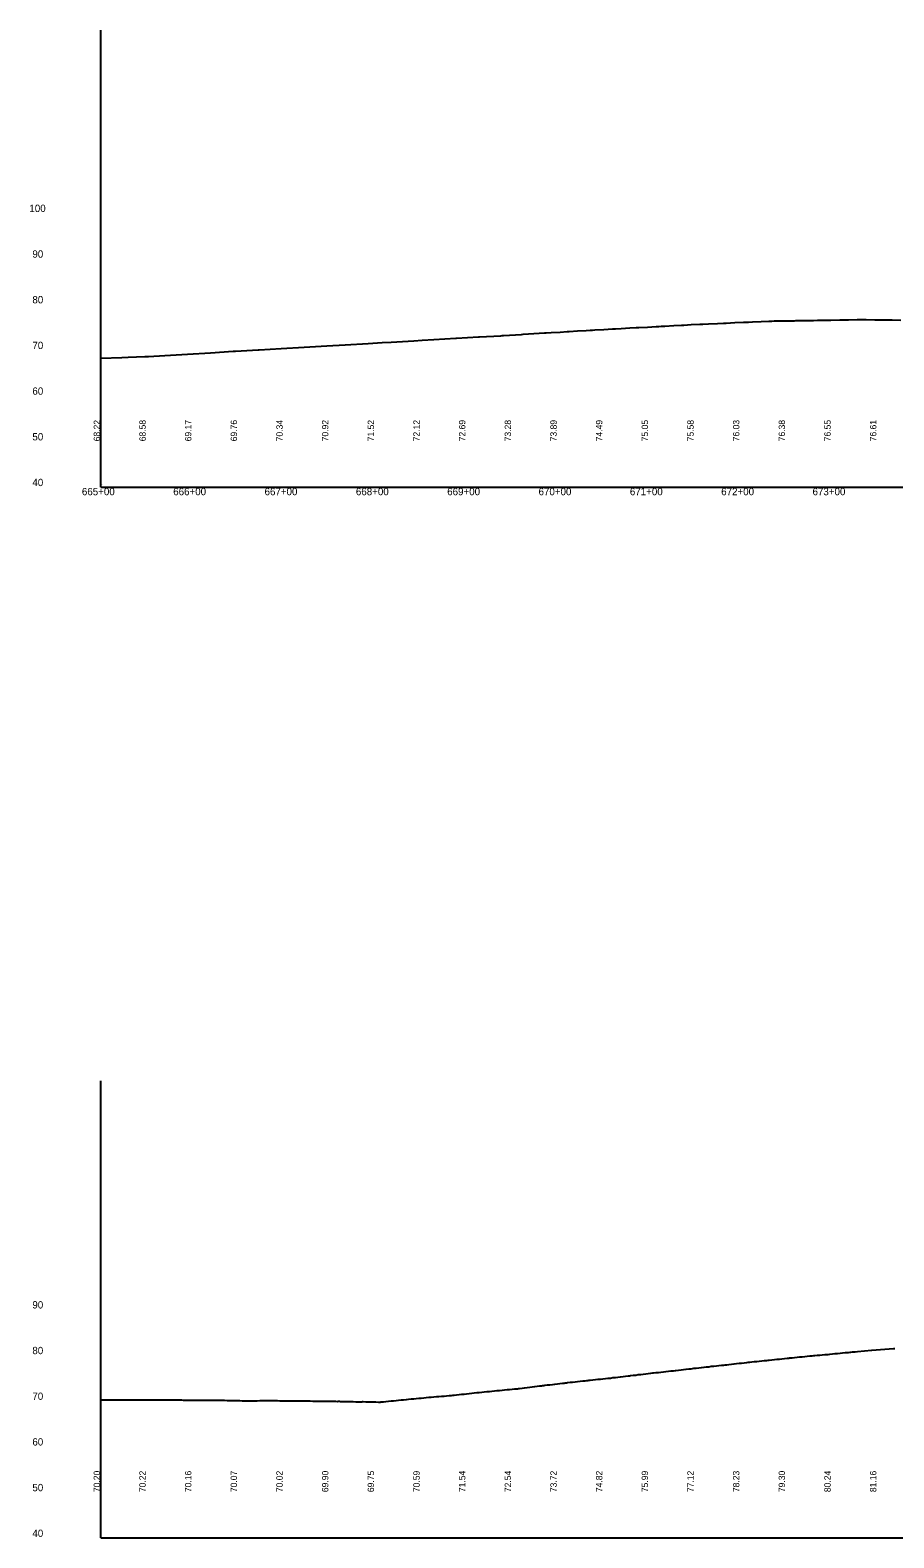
# Model space of a CAD drawing. Extents: x 2526761 to 2530854, y 882903 to 888012.
# Drawn here: x 2526761 to 2527707, y 886362 to 888012 of the extents above; entities that cross this region are included whole.
import ezdxf

# ---------------------------------------------------------------- set-up
doc = ezdxf.new("R2010")
doc.units = 0
for name, color, linetype in [('RD_DDB_ElevTX', 7, 'Continuous'), ('RD_DDB_Profile_EX', 7, 'Continuous'), ('RD_DDB_StaTX', 7, 'Continuous'), ('RD_DDB_StripGrade', 7, 'Continuous'), ('RD_GPK_Profile_Cell', 7, 'Continuous')]:
    doc.layers.add(name, color=color, linetype=linetype)

msp = doc.modelspace()

# ---------------------------------------------------------------- linework, layer by layer
at = {"layer": 'RD_DDB_Profile_EX'}
for points in [[(2526839, 887653.2), (2526862, 887654), (2526868.8, 887654.2), (2526887, 887654.9), (2526891, 887655.1), (2526908.8, 887656.1), (2526933.8, 887657.6), (2526958.8, 887659.1), (2526983.8, 887660.6), (2526986.4, 887660.8), (2527011.3, 887662.2), (2527012.2, 887662.3), (2527036.4, 887663.6), (2527061.4, 887665.1), (2527086.3, 887666.5), (2527106.5, 887667.7), (2527131.5, 887669.2), (2527147, 887670.2), (2527156.6, 887670.8), (2527181.5, 887672.2), (2527190.6, 887672.8), (2527203.3, 887673.5), (2527227.7, 887674.9), (2527228.3, 887674.9), (2527252.2, 887676.3), (2527253.3, 887676.4), (2527276.8, 887677.7), (2527278.3, 887677.8), (2527279.6, 887677.9), (2527299.5, 887679.1), (2527301.1, 887679.2), (2527324.5, 887680.7), (2527326.3, 887680.8), (2527332.1, 887681.1), (2527341.7, 887681.7), (2527349.5, 887682.2), (2527351.5, 887682.3), (2527360.8, 887682.9), (2527370.4, 887683.5), (2527374.5, 887683.7), (2527374.8, 887683.7), (2527377.2, 887683.9), (2527379.9, 887684), (2527389.5, 887684.6), (2527399.1, 887685.1), (2527400.1, 887685.2), (2527402.2, 887685.3), (2527408.6, 887685.6), (2527418.2, 887686.2), (2527425, 887686.6), (2527427.2, 887686.7), (2527427.8, 887686.7), (2527437.3, 887687.2), (2527446.9, 887687.8), (2527449.9, 887687.9), (2527452.2, 887688.1), (2527456.5, 887688.3), (2527466.1, 887688.8), (2527474.7, 887689.3), (2527475.6, 887689.4), (2527477.2, 887689.4), (2527485.2, 887689.8), (2527494.8, 887690.2), (2527496, 887690.3), (2527498, 887690.4), (2527504.3, 887690.7), (2527513.9, 887691.1), (2527520.6, 887691.4), (2527523, 887691.5), (2527523.5, 887691.5), (2527533, 887692), (2527542.6, 887692.4), (2527545.6, 887692.5), (2527548, 887692.6), (2527552.2, 887692.8), (2527561.8, 887693.2), (2527570.4, 887693.6), (2527571.3, 887693.6), (2527573, 887693.7), (2527573.5, 887693.7), (2527576.1, 887693.8), (2527580.9, 887693.9), (2527590.5, 887694), (2527598.5, 887694.1), (2527600, 887694.2), (2527601.1, 887694.2), (2527609.6, 887694.3), (2527619.2, 887694.5), (2527623.5, 887694.6), (2527626.3, 887694.6), (2527628.7, 887694.6), (2527638.3, 887694.8), (2527647.9, 887695), (2527648.4, 887695), (2527651.6, 887695), (2527657.4, 887695.1), (2527667, 887695.3), (2527673.4, 887695.4), (2527676.8, 887695.3), (2527686.2, 887695.2), (2527695.7, 887695)], [(2527695.7, 887695), (2527697.7, 887695), (2527700.7, 887694.9), (2527705.3, 887694.9), (2527714.9, 887694.7)], [(2527543.2, 886553.7), (2527546, 886554), (2527547.5, 886554.2), (2527548.7, 886554.3), (2527549.4, 886554.4), (2527551.5, 886554.6), (2527554.3, 886554.9), (2527557, 886555.2), (2527559.8, 886555.5), (2527562.5, 886555.7), (2527565.3, 886556), (2527567.5, 886556.2), (2527568.1, 886556.3), (2527569.4, 886556.4), (2527570.8, 886556.6), (2527573.6, 886556.9), (2527576.4, 886557.2), (2527579.1, 886557.5), (2527581.9, 886557.8), (2527584.6, 886558.1), (2527587.4, 886558.4), (2527590.2, 886558.7), (2527592.4, 886558.9), (2527592.9, 886559), (2527595.8, 886559.2), (2527598.4, 886559.5), (2527601.2, 886559.8), (2527604, 886560.1), (2527606.7, 886560.3), (2527609.5, 886560.6), (2527612.3, 886560.9), (2527615, 886561.1), (2527617.4, 886561.4), (2527617.8, 886561.4), (2527619.5, 886561.5), (2527620.5, 886561.6), (2527623.3, 886561.9), (2527626.1, 886562.1), (2527628.8, 886562.4), (2527631.6, 886562.6), (2527632.5, 886562.7), (2527634.3, 886562.9), (2527635.2, 886562.9), (2527637.1, 886563.1), (2527639.9, 886563.4), (2527642.6, 886563.7), (2527645.4, 886563.9), (2527648.2, 886564.2), (2527650.9, 886564.5), (2527653.7, 886564.8), (2527656.4, 886565), (2527657.5, 886565.1), (2527659.2, 886565.2), (2527660.1, 886565.3), (2527662, 886565.5), (2527664.7, 886565.7), (2527667.5, 886566), (2527682.5, 886567.4), (2527683.2, 886567.4), (2527706.8, 886569.2), (2527708.2, 886569.3)], [(2527308.5, 886527), (2527311.2, 886527.3), (2527314, 886527.7), (2527316.7, 886528), (2527319.5, 886528.4), (2527321.3, 886528.6), (2527322.3, 886528.7), (2527323.8, 886528.9), (2527325, 886529), (2527327.8, 886529.4), (2527330.6, 886529.7), (2527333.3, 886530), (2527336.1, 886530.4), (2527338.8, 886530.7), (2527341.6, 886531), (2527344.4, 886531.3), (2527346, 886531.5), (2527347.1, 886531.6), (2527349.3, 886531.9), (2527349.9, 886532), (2527352.6, 886532.3), (2527355.4, 886532.6), (2527358.2, 886532.9), (2527360.9, 886533.2), (2527363.7, 886533.5), (2527366.5, 886533.8), (2527369.2, 886534.1), (2527371, 886534.3), (2527372, 886534.4), (2527373.3, 886534.6), (2527374.7, 886534.7), (2527377.5, 886535), (2527380.3, 886535.3), (2527383, 886535.6), (2527385.8, 886535.9), (2527388.5, 886536.1), (2527391.3, 886536.4), (2527394.1, 886536.7), (2527394.6, 886536.8), (2527396.8, 886537), (2527399.6, 886537.4), (2527402.4, 886537.7), (2527405.1, 886538), (2527407.9, 886538.4), (2527410.6, 886538.7), (2527413.4, 886539), (2527416.2, 886539.3), (2527417.2, 886539.4), (2527417.7, 886539.5), (2527418.9, 886539.7), (2527421.7, 886540), (2527424.5, 886540.3), (2527427.2, 886540.7), (2527430, 886541), (2527432.7, 886541.3), (2527435.5, 886541.6), (2527438.3, 886541.9), (2527441, 886542.3), (2527443.2, 886542.6), (2527443.8, 886542.6), (2527446.5, 886542.9), (2527449.3, 886543.2), (2527452.1, 886543.5), (2527454.8, 886543.8), (2527457.6, 886544.1), (2527460.4, 886544.4), (2527463.1, 886544.7), (2527466, 886545), (2527468.2, 886545.3), (2527468.6, 886545.3), (2527471.4, 886545.6), (2527474.3, 886545.9), (2527476.9, 886546.2), (2527479.7, 886546.6), (2527482.5, 886546.9), (2527485.2, 886547.2), (2527488, 886547.6), (2527490.7, 886547.9), (2527493.5, 886548.2), (2527496.3, 886548.5), (2527496.7, 886548.6), (2527499, 886548.8), (2527499.3, 886548.9), (2527501.8, 886549.1), (2527504.5, 886549.4), (2527507.3, 886549.8), (2527510.1, 886550.1), (2527512.8, 886550.3), (2527515.6, 886550.6), (2527518.4, 886550.9), (2527521.1, 886551.2), (2527522.5, 886551.4), (2527523.9, 886551.5), (2527524.4, 886551.6), (2527526.6, 886551.8), (2527529.4, 886552.1), (2527532.2, 886552.5), (2527534.9, 886552.8), (2527537.7, 886553.1), (2527540.4, 886553.4), (2527543.2, 886553.7)], [(2526839, 886513.1), (2526841.7, 886513.1), (2526844.5, 886513.1), (2526847.2, 886513.1), (2526850, 886513.1), (2526852.8, 886513.1), (2526855.7, 886513.1), (2526856.9, 886513.1), (2526858.3, 886513.1), (2526861, 886513.1), (2526863.8, 886513.2), (2526866.6, 886513.2), (2526869.3, 886513.2), (2526872.1, 886513.2), (2526874.9, 886513.2), (2526877.6, 886513.2), (2526880.4, 886513.2), (2526880.8, 886513.2), (2526883.1, 886513.2), (2526884.5, 886513.2), (2526884.9, 886513.2), (2526885.9, 886513.2), (2526888.7, 886513.2), (2526891.4, 886513.2), (2526894.2, 886513.2), (2526897, 886513.1), (2526899.7, 886513.1), (2526902.5, 886513.1), (2526905.2, 886513.1), (2526907, 886513.1), (2526908, 886513.1), (2526910.9, 886513.1), (2526913.5, 886513.1), (2526916.3, 886513), (2526919, 886513), (2526921.8, 886513), (2526924.6, 886513), (2526927.3, 886513), (2526929.1, 886512.9), (2526930.1, 886512.9), (2526932.9, 886512.9), (2526935.6, 886512.9), (2526937.4, 886512.9), (2526938.4, 886512.9), (2526941.1, 886512.9), (2526943.9, 886512.8), (2526946.7, 886512.8), (2526949.4, 886512.8), (2526950.5, 886512.8), (2526952.2, 886512.8), (2526954.9, 886512.7), (2526957.7, 886512.7), (2526960.5, 886512.7), (2526963.2, 886512.7), (2526964.6, 886512.7), (2526966, 886512.7), (2526968.8, 886512.6), (2526971.5, 886512.6), (2526974.3, 886512.6), (2526977, 886512.5), (2526979.8, 886512.5), (2526982.6, 886512.5), (2526985.3, 886512.5), (2526988.5, 886512.5), (2526990.9, 886512.4), (2526993.6, 886512.2), (2526996.4, 886512.1), (2526999.1, 886512), (2526999.9, 886512), (2527001.9, 886512), (2527004.7, 886512.1), (2527007.4, 886512.2), (2527010.2, 886512.2), (2527012.9, 886512.3), (2527015.7, 886512.4), (2527018, 886512.4), (2527018.5, 886512.4), (2527021.2, 886512.4), (2527023, 886512.3), (2527024, 886512.3), (2527024.7, 886512.3), (2527026.8, 886512.3), (2527029.5, 886512.3), (2527032.3, 886512.3), (2527035, 886512.2), (2527037.8, 886512.2), (2527040.6, 886512.2), (2527043.3, 886512.1), (2527046.1, 886512.1), (2527047.1, 886512.1), (2527048.8, 886512.1), (2527051.1, 886512.1), (2527051.6, 886512.1), (2527054.4, 886512), (2527057.1, 886512), (2527059.9, 886512), (2527062.7, 886511.9), (2527065.4, 886511.9), (2527068.2, 886511.9), (2527070.9, 886511.8), (2527073.7, 886511.8)], [(2527073.7, 886511.8), (2527075.3, 886511.8), (2527076.5, 886511.8), (2527079.2, 886511.7), (2527082, 886511.7), (2527084.8, 886511.6), (2527087.5, 886511.6), (2527090.3, 886511.6), (2527093, 886511.5), (2527095.8, 886511.5), (2527097.7, 886511.4), (2527098.6, 886511.5), (2527100, 886511.5), (2527101.3, 886511.4), (2527104.1, 886511.4), (2527106.8, 886511.3), (2527109.6, 886511.3), (2527112.4, 886511.2), (2527115.1, 886511.2), (2527117.9, 886511.1), (2527120.7, 886511.1), (2527123.4, 886511), (2527125, 886511.1), (2527125.5, 886511.2), (2527126.2, 886511.2), (2527128.9, 886511.1), (2527131.7, 886511), (2527134.5, 886510.9), (2527137.2, 886510.9), (2527140, 886510.8), (2527142.8, 886510.7), (2527144.5, 886510.7), (2527145, 886510.7), (2527145.5, 886510.8), (2527147.1, 886510.9), (2527148.3, 886511.1), (2527151, 886511.4), (2527153.8, 886511.6), (2527156.6, 886511.9), (2527159.3, 886512.2), (2527162.1, 886512.5), (2527164.8, 886512.7), (2527167.6, 886513), (2527170, 886513.3), (2527170.4, 886513.3), (2527173.1, 886513.6), (2527173.5, 886513.6), (2527175.9, 886513.8), (2527178.7, 886514.1), (2527181.4, 886514.4), (2527184.2, 886514.6), (2527186.9, 886514.9), (2527189.7, 886515.1), (2527192.5, 886515.4), (2527195.2, 886515.6), (2527198, 886515.9), (2527198.3, 886515.9), (2527200.7, 886516.1), (2527203.5, 886516.4), (2527206.3, 886516.6), (2527209, 886516.8), (2527211.8, 886517.1), (2527214.6, 886517.3), (2527217.3, 886517.5), (2527220.1, 886517.7), (2527222.5, 886517.9), (2527222.8, 886518), (2527224.4, 886518.2), (2527225.6, 886518.3), (2527228.4, 886518.6), (2527231.1, 886518.9), (2527233.9, 886519.2), (2527236.7, 886519.5), (2527239.4, 886519.8), (2527242.2, 886520.1), (2527244.9, 886520.4), (2527247.7, 886520.7), (2527250.5, 886521), (2527253.2, 886521.3), (2527256, 886521.6), (2527258.7, 886521.9), (2527261.5, 886522.1), (2527264.3, 886522.4), (2527267, 886522.7), (2527269.8, 886523), (2527272.6, 886523.2), (2527275.3, 886523.5), (2527278.1, 886523.8), (2527280.8, 886524), (2527283.6, 886524.3), (2527286.4, 886524.5), (2527289.1, 886524.8), (2527291.9, 886525), (2527294.6, 886525.3), (2527295.2, 886525.3), (2527296.3, 886525.4), (2527297.4, 886525.6), (2527300.2, 886525.9), (2527302.9, 886526.3), (2527305.7, 886526.6), (2527308.5, 886527)]]:
    msp.add_lwpolyline(points, dxfattribs=at)
at = {"layer": 'RD_GPK_Profile_Cell'}
for p, q in [((2526839, 887512.1), (2526839, 888012.1)), ((2526839, 887512.1), (2530839, 887512.1)), ((2526839, 887512.1), (2526839, 887512.1)), ((2526839, 886362.1), (2526839, 886862.1)), ((2526839, 886362.1), (2528539, 886362.1)), ((2526839, 886362.1), (2526839, 886362.1))]:
    msp.add_line(p, q, dxfattribs=at)

# ---------------------------------------------------------------- texts
at = {"layer": 'RD_DDB_ElevTX'}
for s, p in [('100', (2526760.6, 887813.1)), ('90', (2526763.9, 887763.1)), ('80', (2526763.9, 887713.1)), ('70', (2526763.9, 887663.1)), ('60', (2526763.9, 887613.1)), ('50', (2526763.9, 887563.1)), ('40', (2526763.9, 887513.1)), ('90', (2526763.9, 886613.1)), ('80', (2526763.9, 886563.1)), ('70', (2526763.9, 886513.1)), ('60', (2526763.9, 886463.1)), ('50', (2526763.9, 886413.1)), ('40', (2526763.9, 886363.1))]:
    msp.add_text(s, height=8, dxfattribs=at).set_placement(p)
at = {"layer": 'RD_DDB_StaTX'}
for s, p in [('665+00', (2526818.1, 887503.1)), ('666+00', (2526918.1, 887503.1)), ('667+00', (2527018.1, 887503.1)), ('668+00', (2527118.1, 887503.1)), ('669+00', (2527218.1, 887503.1)), ('670+00', (2527318.1, 887503.1)), ('671+00', (2527418.1, 887503.1)), ('672+00', (2527518.1, 887503.1)), ('673+00', (2527618.1, 887503.1))]:
    msp.add_text(s, height=8, dxfattribs=at).set_placement(p)
at = {"layer": 'RD_DDB_StripGrade'}
for s, p in [('68.22', (2526838, 887562.1)), ('68.58', (2526888, 887562.1)), ('69.17', (2526938, 887562.1)), ('69.76', (2526988, 887562.1)), ('70.34', (2527038, 887562.1)), ('70.92', (2527088, 887562.1)), ('71.52', (2527138, 887562.1)), ('72.12', (2527188, 887562.1)), ('72.69', (2527238, 887562.1)), ('73.28', (2527288, 887562.1)), ('73.89', (2527338, 887562.1)), ('74.49', (2527388, 887562.1)), ('75.05', (2527438, 887562.1)), ('75.58', (2527488, 887562.1)), ('76.03', (2527538, 887562.1)), ('76.38', (2527588, 887562.1)), ('76.55', (2527638, 887562.1)), ('76.61', (2527688, 887562.1)), ('70.20', (2526838, 886412.1)), ('70.22', (2526888, 886412.1)), ('70.16', (2526938, 886412.1)), ('70.07', (2526988, 886412.1)), ('70.02', (2527038, 886412.1)), ('69.90', (2527088, 886412.1)), ('69.75', (2527138, 886412.1)), ('70.59', (2527188, 886412.1)), ('71.54', (2527238, 886412.1)), ('72.54', (2527288, 886412.1)), ('73.72', (2527338, 886412.1)), ('74.82', (2527388, 886412.1)), ('75.99', (2527438, 886412.1)), ('77.12', (2527488, 886412.1)), ('78.23', (2527538, 886412.1)), ('79.30', (2527588, 886412.1)), ('80.24', (2527638, 886412.1)), ('81.16', (2527688, 886412.1))]:
    msp.add_text(s, height=7, rotation=90, dxfattribs=at).set_placement(p)
at = {"layer": 'RD_GPK_Profile_Cell'}
for s, p in [('059', (2526839, 887516.5)), ('SC41', (2526839, 887515.8)), ('66500.000000', (2526839, 887515.2)), ('40', (2526839, 887514.6)), ('50', (2526839, 887514)), ('10', (2526839, 887513.3)), ('NOGAP', (2526839, 887512.7)), ('059', (2526839, 886366.5)), ('SC917', (2526839, 886365.8)), ('0.000000', (2526839, 886365.2)), ('40', (2526839, 886364.6)), ('50', (2526839, 886364)), ('10', (2526839, 886363.3)), ('NOGAP', (2526839, 886362.7))]:
    msp.add_text(s, height=0.208, dxfattribs=at).set_placement(p)

doc.saveas('drawing.dxf')
